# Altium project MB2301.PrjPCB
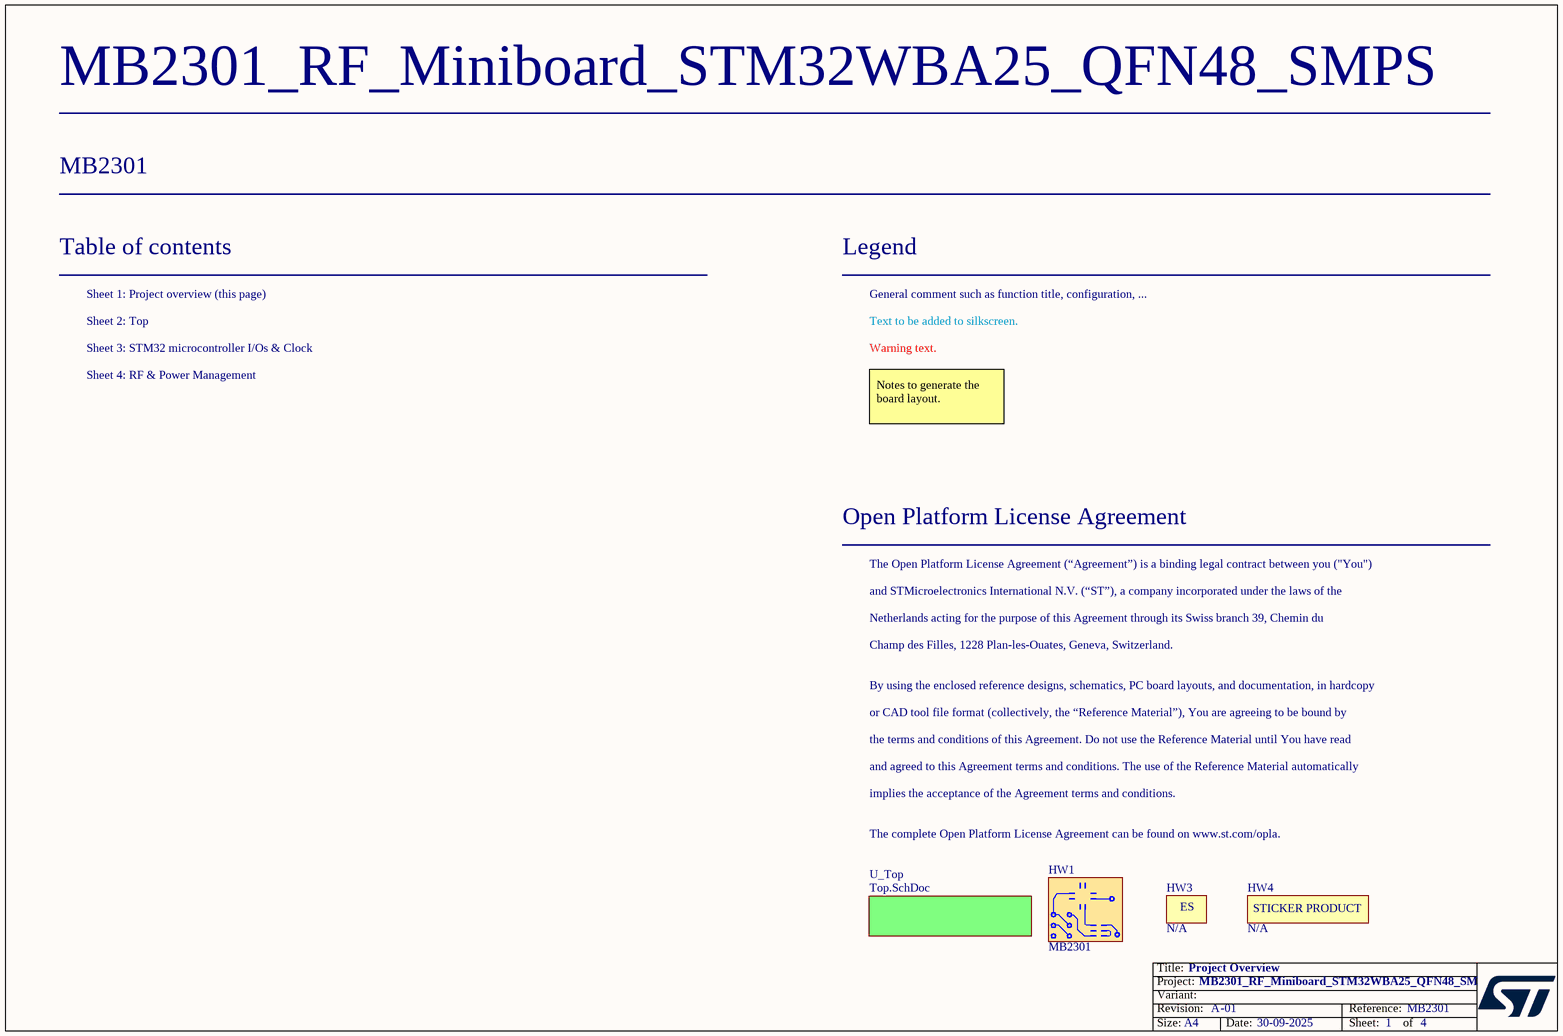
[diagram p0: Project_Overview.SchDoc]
Board_Assembly_Revision: 01; Board_Document_Date: 30-09-2025; Board_Name: MB2301_RF_Miniboard_STM32WBA25_QFN48_SMPS; Board_PCB_Revision: A; Board_Reference: MB2301
4 sheets, 104 parts. Net scope: flat (ports and power ports of the same name join across sheets).
Board file: MB2301.PcbDoc
Sheets:
  Project_Overview.SchDoc
    U_Top = Top.SchDoc
      STM32 microcontroller I/Os & Clock = MCU.SchDoc
      RF & Power Management Schematic = RF&Power_Management.SchDoc

## Sheet Project_Overview.SchDoc: Project Overview
size A4; Date: Not used; ApprovedBy: Not used; CheckedBy: Not used; Author: Not used; CompanyName: STMicroelectronics; DrawnBy: Not used; Engineer: Not used; Organization: Not used; Address1: Not used; Address2: Not used; Address3: Not used; Address4: Not used; DocumentNumber: 1; Revision: Not used; SheetNumber: 1; SheetTotal: 4

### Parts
HW1  MB2301  (mechanical)
HW3  STICKER_ES  [STICKER_ES_6X6]  (value not drawn)  (no BOM)
HW4  STICKER_PRODUCT  [STICKER_PRODUCT_25X9]  (value not drawn)  (no BOM)

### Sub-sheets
U_Top = Top.SchDoc: no entries

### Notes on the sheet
- Table of contents
- Sheet 1: Project overview (this page)
- Legend
- General comment such as function title, configuration, ...
- Sheet 2: Top
- Sheet 3: STM32 microcontroller I/Os & Clock
- Sheet 4: RF & Power Management
- Text to be added to silkscreen.
- Warning text.
- Notes to generate the board layout.
- Open Platform License Agreement
- The Open Platform License Agreement (“Agreement”) is a binding legal contract between you ("You")
- and STMicroelectronics International N.V. (“ST”), a company incorporated under the laws of the
- Netherlands acting for the purpose of this Agreement through its Swiss branch 39, Chemin du
- Champ des Filles, 1228 Plan-les-Ouates, Geneva, Switzerland.
- By using the enclosed reference designs, schematics, PC board layouts, and documentation, in hardcopy
- or CAD tool file format (collectively, the “Reference Material”), You are agreeing to be bound by
- the terms and conditions of this Agreement. Do not use the Reference Material until You have read
- and agreed to this Agreement terms and conditions. The use of the Reference Material automatically
- implies the acceptance of the Agreement terms and conditions.
- The complete Open Platform License Agreement can be found on www.st.com/opla.

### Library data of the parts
HW1 = MB2301: PCB2301 for include in BOM; Internal_Part_Number: MCD-04979; Manufacturer: FASTPRINT; Part_Preference: Recommended; ECCN_EU: NEC°°°; ECCN_US: EAR99°°°; CCATS: Not Required
HW3 = MCD-00234: Sticker ES, 6x6mm; Part_Type: Misc; Part_Preference: Recommended; Component_Country_Of_Origin: Unknown; ShowFields: YES; ID: 2634
HW4 = MCD-00547: Sticker product, 25x9mm; Part_Type: Misc; Part_Preference: Recommended; Component_Country_Of_Origin: Unknown; ShowFields: YES; ID: 3197

## Sheet Top.SchDoc: Top Schematic
size A4; Date: Not used; ApprovedBy: Not used; CheckedBy: Not used; Author: Not used; CompanyName: STMicroelectronics; DrawnBy: Not used; Engineer: Not used; Organization: Not used; Address1: Not used; Address2: Not used; Address3: Not used; Address4: Not used; DocumentNumber: 2; Revision: Not used; SheetNumber: 2; SheetTotal: 4
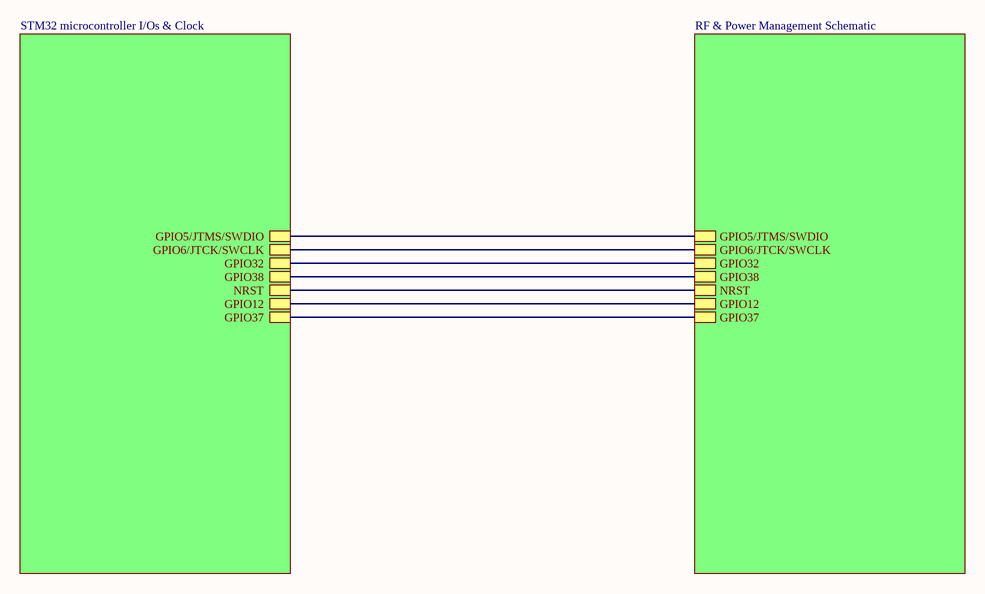
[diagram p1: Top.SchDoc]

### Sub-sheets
RF & Power Management Schematic = RF&Power_Management.SchDoc: GPIO5/JTMS/SWDIO, GPIO6/JTCK/SWCLK, GPIO32, GPIO38, NRST, GPIO12, GPIO37
STM32 microcontroller I/Os & Clock = MCU.SchDoc: GPIO37, GPIO5/JTMS/SWDIO, GPIO6/JTCK/SWCLK, GPIO32, GPIO38, NRST, GPIO12

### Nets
(unnamed): sheet STM32 microcontroller I/Os & Clock/GPIO37, sheet RF & Power Management Schematic/GPIO37
(unnamed): sheet STM32 microcontroller I/Os & Clock/GPIO5/JTMS/SWDIO, sheet RF & Power Management Schematic/GPIO5/JTMS/SWDIO  [a separate net that carries the same name]
(unnamed): sheet STM32 microcontroller I/Os & Clock/GPIO6/JTCK/SWCLK, sheet RF & Power Management Schematic/GPIO6/JTCK/SWCLK  [a separate net that carries the same name]
(unnamed): sheet STM32 microcontroller I/Os & Clock/GPIO32, sheet RF & Power Management Schematic/GPIO32  [a separate net that carries the same name]
(unnamed): sheet STM32 microcontroller I/Os & Clock/GPIO38, sheet RF & Power Management Schematic/GPIO38  [a separate net that carries the same name]
(unnamed): sheet STM32 microcontroller I/Os & Clock/NRST, sheet RF & Power Management Schematic/NRST  [a separate net that carries the same name]
(unnamed): sheet STM32 microcontroller I/Os & Clock/GPIO12, sheet RF & Power Management Schematic/GPIO12  [a separate net that carries the same name]

## Sheet MCU.SchDoc: STM32 microcontroller I/Os & Clock
size A4; Date: Not used; ApprovedBy: Not used; CheckedBy: Not used; Author: Not used; CompanyName: STMicroelectronics; DrawnBy: Not used; Engineer: Not used; Organization: Not used; Address1: Not used; Address2: Not used; Address3: Not used; Address4: Not used; DocumentNumber: 3; Revision: Not used; SheetNumber: 3; SheetTotal: 4
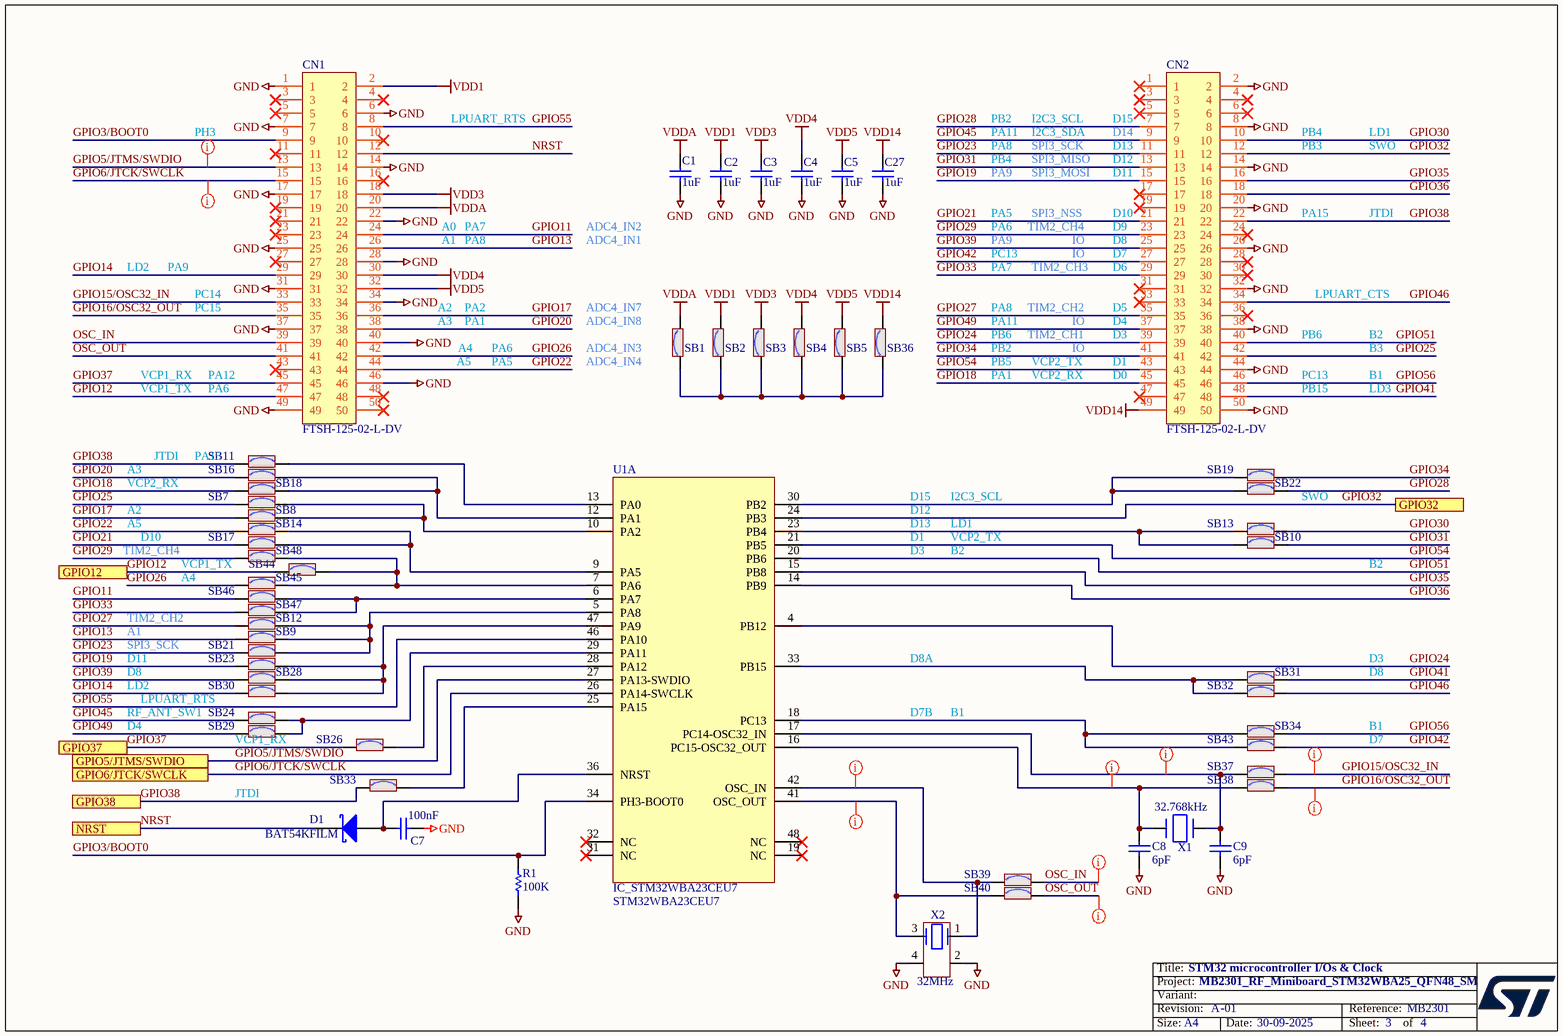
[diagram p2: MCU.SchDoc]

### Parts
C1  value 1uF  [C0402]  (hidden comment: Capacitor)
C2  value 1uF  [C0402]  (hidden comment: Capacitor)
C3  value 1uF  [C0402]  (hidden comment: Capacitor)
C4  value 1uF  [C0402]  (hidden comment: Capacitor)
C5  value 1uF  [C0402]  (hidden comment: Capacitor)
C7  value 100nF  [C0402]  (hidden comment: Capacitor)
C8  value 6pF  [C0402]  (hidden comment: Capacitor)
C9  value 6pF  [C0402]  (hidden comment: Capacitor)
C27  value 1uF  [C0402]  (hidden comment: Capacitor)
CN1  FTSH-125-02-L-DV  [Footprint sent by email... (Footprint FTSH-125-02-L-DV)]
CN2  FTSH-125-02-L-DV  [Footprint sent by email... (Footprint FTSH-125-02-L-DV)]
D1  value BAT54KFILM  [DIO_SOD523_1A_2K]  (hidden comment: SCHOTTKY_1A_2K)
R1  value 100K  [R0402]  (hidden comment: Resistor)
SB1  SB_ON  [SOLDER-BRIDGE_R0402-0R]  (value not drawn)
SB2  SB_ON  [SOLDER-BRIDGE_R0402-0R]  (value not drawn)
SB3  SB_ON  [SOLDER-BRIDGE_R0402-0R]  (value not drawn)
SB4  SB_ON  [SOLDER-BRIDGE_R0402-0R]  (value not drawn)
SB5  SB_ON  [SOLDER-BRIDGE_R0402-0R]  (value not drawn)
SB7  SB_ON  [SOLDER-BRIDGE_R0402-0R]  (value not drawn)
SB8  SB_ON  [SOLDER-BRIDGE_R0402-0R]  (value not drawn)
SB9  SB_ON  [SOLDER-BRIDGE_R0402-0R]  (value not drawn)
SB10  SB_ON  [SOLDER-BRIDGE_R0402-0R]  (value not drawn)
SB11  SB_ON  [SOLDER-BRIDGE_R0402-0R]  (value not drawn)
SB12  SB_ON  [SOLDER-BRIDGE_R0402-0R]  (value not drawn)
SB13  SB_ON  [SOLDER-BRIDGE_R0402-0R]  (value not drawn)
SB14  SB_ON  [SOLDER-BRIDGE_R0402-0R]  (value not drawn)
SB16  SB_ON  [SOLDER-BRIDGE_R0402-0R]  (value not drawn)
SB17  SB_ON  [SOLDER-BRIDGE_R0402-0R]  (value not drawn)
SB18  SB_ON  [SOLDER-BRIDGE_R0402-0R]  (value not drawn)
SB19  SB_ON  [SOLDER-BRIDGE_R0402-0R]  (value not drawn)
SB21  SB_ON  [SOLDER-BRIDGE_R0402-0R]  (value not drawn)
SB22  SB_ON  [SOLDER-BRIDGE_R0402-0R]  (value not drawn)
SB23  SB_ON  [SOLDER-BRIDGE_R0402-0R]  (value not drawn)
SB24  SB_ON  [SOLDER-BRIDGE_R0402-0R]  (value not drawn)
SB26  SB_ON  [SOLDER-BRIDGE_R0402-0R]  (value not drawn)
SB28  SB_ON  [SOLDER-BRIDGE_R0402-0R]  (value not drawn)
SB29  SB_ON  [SOLDER-BRIDGE_R0402-0R]  (value not drawn)
SB30  SB_ON  [SOLDER-BRIDGE_R0402-0R]  (value not drawn)
SB31  SB_ON  [SOLDER-BRIDGE_R0402-0R]  (value not drawn)
SB32  SB_ON  [SOLDER-BRIDGE_R0402-0R]  (value not drawn)
SB33  SB_ON  [SOLDER-BRIDGE_R0402-0R]  (value not drawn)
SB34  SB_ON  [SOLDER-BRIDGE_R0402-0R]  (value not drawn)
SB36  SB_ON  [SOLDER-BRIDGE_R0402-0R]  (value not drawn)
SB37  SB_ON  [SOLDER-BRIDGE_R0402-0R]  (value not drawn)
SB38  SB_ON  [SOLDER-BRIDGE_R0402-0R]  (value not drawn)
SB39  SB_ON  [SOLDER-BRIDGE_R0402-0R]  (value not drawn)
SB40  SB_ON  [SOLDER-BRIDGE_R0402-0R]  (value not drawn)
SB43  SB_ON  [SOLDER-BRIDGE_R0402-0R]  (value not drawn)
SB44  SB_ON  [SOLDER-BRIDGE_R0402-0R]  (value not drawn)
SB45  SB_ON  [SOLDER-BRIDGE_R0402-0R]  (value not drawn)
SB46  SB_ON  [SOLDER-BRIDGE_R0402-0R]  (value not drawn)
SB47  SB_ON  [SOLDER-BRIDGE_R0402-0R]  (value not drawn)
SB48  SB_ON  [SOLDER-BRIDGE_R0402-0R]  (value not drawn)
U1  IC_STM32WBA23CEU7  value STM32WBA23CEU7  [ICC_UFQFPN48-EPAD_7X7_H0P55_P050]  (part A of 3)
X1  value 32.768kHz  [CRY_NX1610SE_2P]  (hidden comment: XTAL_2_PINS)
X2  value 32MHz  [CRY_NX1612SA_4P]  (hidden comment: XTAL_4_PINS)

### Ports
GPIO5/JTMS/SWDIO, GPIO6/JTCK/SWCLK, GPIO12, GPIO32, GPIO37, GPIO38, NRST

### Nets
GND: C1.1 C2.1 C3.1 C4.1 C5.1 C7.1 C8.2 C9.1 C27.1 CN1.1 CN1.6 CN1.7 CN1.14 CN1.17 CN1.22 CN1.25 CN1.28 CN1.31 CN1.34 CN1.37 CN1.40 CN1.46 CN1.49 CN2.2 CN2.8 CN2.14 CN2.20 CN2.26 CN2.32 CN2.38 CN2.44 CN2.50 R1.2 X2.2 X2.4
VDD1: C2.2 CN1.2 SB2.2
VDD3: C3.2 CN1.18 SB3.2
VDD4: C4.2 CN1.30 SB4.2
VDD5: C5.2 CN1.32 SB5.2
VDD14: C27.2 CN2.49 SB36.2
VDDA: C1.2 CN1.20 SB1.2
GPIO3/BOOT0: CN1.9 R1.1 U1.34(PH3-BOOT0)
GPIO5/JTMS/SWDIO: CN1.13 U1.27(PA13-SWDIO) ; port GPIO5/JTMS/SWDIO
GPIO6/JTCK/SWCLK: CN1.15 U1.26(PA14-SWCLK) ; port GPIO6/JTCK/SWCLK
GPIO11: CN1.24 SB46.1
GPIO12: CN1.47 SB44.1 ; port GPIO12
GPIO13: CN1.26 SB9.1
GPIO14: CN1.29 SB30.1
GPIO15/OSC32_IN: CN1.33 SB37.2
GPIO16/OSC32_OUT: CN1.35 SB38.2
GPIO17: CN1.36 SB8.1
GPIO18: CN2.45 SB18.1
GPIO19: CN2.15 SB23.1
GPIO20: CN1.38 SB16.1
GPIO21: CN2.21 SB17.1
GPIO22: CN1.44 SB14.1
GPIO23: CN2.11 SB21.1
GPIO24: CN2.39 U1.4(PB12)
GPIO25: CN2.42 SB7.1
GPIO26: CN1.42 SB45.1
GPIO27: CN2.35 SB12.1
GPIO28: CN2.7 SB22.2
GPIO29: CN2.23 SB48.1
GPIO30: CN2.10 SB13.2
GPIO31: CN2.13 SB10.2
GPIO32: CN2.12 U1.24(PB3) ; port GPIO32
GPIO33: CN2.29 SB47.1
GPIO34: CN2.41 SB19.2
GPIO35: CN2.16 U1.15(PB8)
GPIO36: CN2.18 U1.14(PB9)
GPIO37: CN1.45 SB26.1 ; port GPIO37
GPIO38: CN2.22 SB11.1 SB33.1 ; port GPIO38
GPIO39: CN2.25 SB28.1
GPIO41: CN2.48 SB31.2
GPIO42: CN2.27 SB43.2
GPIO45: CN2.9 SB24.1
GPIO46: CN2.34 SB32.2
GPIO49: CN2.37 SB29.1
GPIO51: CN2.40 U1.20(PB6)
GPIO54: CN2.43 U1.21(PB5)
GPIO55: CN1.8 U1.46(PA10)
GPIO56: CN2.46 SB34.2
NRST: CN1.12 D1.2(K) ; port NRST
OSC_IN: CN1.39 SB39.2
OSC_OUT: CN1.41 SB40.2
NetC7_2: C7.2 D1.1(A) U1.36(NRST)
NetC8_1: C8.1 SB38.1 U1.16(PC15-OSC32_OUT) X1.2(X2)
NetC9_2: C9.2 SB37.1 U1.17(PC14-OSC32_IN) X1.1(X1)
NetSB1_1: SB1.1 SB2.1 SB3.1 SB4.1 SB5.1 SB36.1
NetSB7_2: SB7.2 SB8.2 U1.10(PA2)
NetSB9_2: SB9.2 SB12.2 SB21.2 U1.5(PA8)
NetSB10_1: SB10.1 SB13.1 U1.23(PB4)
NetSB11_2: SB11.2 U1.13(PA0)
NetSB14_2: SB14.2 SB17.2 U1.9(PA5)
NetSB16_2: SB16.2 SB18.2 U1.12(PA1)
NetSB19_1: SB19.1 SB22.1 U1.30(PB2)
NetSB23_2: SB23.2 SB28.2 SB30.2 U1.47(PA9)
NetSB24_2: SB24.2 SB29.2 U1.29(PA11)
NetSB26_2: SB26.2 U1.28(PA12)
NetSB31_1: SB31.1 SB32.1 U1.33(PB15)
NetSB33_2: SB33.2 U1.25(PA15)
NetSB34_1: SB34.1 SB43.1 U1.18(PC13)
NetSB39_1: SB39.1 U1.42(OSC_IN) X2.1
NetSB40_1: SB40.1 U1.41(OSC_OUT) X2.3
NetSB44_2: SB44.2 SB45.2 SB48.2 U1.7(PA6)
NetSB46_2: SB46.2 SB47.2 U1.6(PA7)

Not connected (* = marked no-connect by the designer): CN1 3* 4* 5* 10* 11* 16* 19* 21* 23* 27* 43* 48* 50*; CN2 1* 3* 4* 5* 6* 17* 19* 24* 28* 30* 31* 33* 36* 47*; U1 19(NC)* 31(NC)* 32(NC)* 48(NC)*

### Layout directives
net class X2: NetSB39_1, NetSB40_1, OSC_IN, OSC_OUT
net class X1: GPIO15/OSC32_IN, GPIO16/OSC32_OUT, NetC8_1, NetC9_2
net class SWCLK: GPIO6/JTCK/SWCLK
net class SWDIO: GPIO5/JTMS/SWDIO

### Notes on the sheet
- PH3
- LPUART_RTS
- PA8
- PB2
- PB4
- PA11
- PA9
- I2C3_SDA
- I2C3_SCL
- SPI3_SCK
- SPI3_MISO
- SPI3_MOSI
- (near CN2) D11
- (near CN2) D13
- (near CN2) D15
- (near CN2) D12
- (near CN2) D14
- PB3
- SWO
- LD1
- A0
- A1
- PA7
- ADC4_IN2
- ADC4_IN1
- PA5
- PA6
- TIM2_CH4
- SPI3_NSS
- IO
- (near CN2) D10
- (near CN2) D9
- (near CN2) D8
- PA15
- JTDI
- LD2
- PC14
- PC15
- A2
- PA2
- (near SB1) ADC4_IN7
- PC13
- TIM2_CH2
- TIM2_CH3
- (near CN2) D7
- (near CN2) D5
- (near CN2) D6
- LPUART_CTS
- VCP1_RX
- PA12
- A3
- A5
- A4
- PA1
- (near SB1) ADC4_IN8
- (near SB1) ADC4_IN4
- (near SB1) ADC4_IN3
- PB5
- PB6
- TIM2_CH1
- VCP2_TX
- VCP2_RX
- (near CN2) D1
- (near CN2) D4
- (near CN2) D3
- (near CN2) D0
- B1
- B2
- B3
- VCP1_TX
- PB15
- LD3
- D12
- D15
- D10
- D3
- D1
- D13
- RF_ANT_SW1
- D8
- D11
- D7B
- D8A
- D4
- (near SB29) VCP1_RX
- D7

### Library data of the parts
C1-C5 C27 = MCD-01722: Capacitor, MLCC, 1uF, 10V, X5R, +/-10%, 0402, T=0.5mm; Part_Preference: Recommended; Manufacturer: YAGEO; Manufacturer_Part_Number: CC0402KRX5R6BB105; Component_Country_Of_Origin: China
C7 = MCD-00006: Capacitor, MLCC, 100nF, 16V, X7R, +/-10%, 0402, T=0.5mm; Manufacturer_Part_Number: CC0402KRX7R7BB104; Manufacturer: YAGEO; Alternate_Manufacturer_Part_Number: GCM155R71C104KA55D; Alternate_Manufacturer: MURATA; Part_Preference: Recommended; Order_Code_RS: 616-9701
C8 C9 = MCD-03185: Capacitor, MLCC, 6 pF, 50V, NPO, ±0,25pF, 0402, T=0.5mm; Part_Preference: Recommended; Manufacturer: MURATA; Manufacturer_Part_Number: GJM1555C1H6R0CB01; Order_Code_RS: 170-6040; ShowFields: YES; ID: 5301
CN1 CN2 = MCD-02746: Header 25x2, 12.7mm, SMT,height 4.83mm; Part_Type: Connector; Part_Preference: Recommended; Manufacturer: SAMTEC; Order_code_RS: NA; ShowFields: YES; ID: 4858
D1 = MCD-01677: Small signal Schottky diodes; Part_Type: Diode; Manufacturer: STMICROELECTRONICS; BMS_Part_Number: 9151123; Part_Preference: Recommended; Manufacturer_HQ_COO: EU
R1 = MCD-00059: Resistor, 100K, 0402, +/-1%, 1/16W; Part_Preference: Recommended; Manufacturer: YAGEO; Manufacturer_Part_Number: RC0402FR-07100KL; Component_Country_Of_Origin: China
SB1-SB5 SB7-SB14 SB16-SB19 SB21-SB24 SB26 SB28-SB34 SB36-SB40 SB43-SB48 = MCD-01618: Solder Bridge 0402 ON; Part_Type: Misc; Part_Preference: Recommended; Manufacturer: YAGEO; Manufacturer_Part_Number: RC0402JR-070RL; Order_Code_RS: 618-5804; Component_Country_Of_Origin: China
U1 = MCD-04358: MCU, ARM Cortex-M33 32-bit, 512KB Flash, 96KB RAM, Crypto, SMPS; Part_Type: IC; Part_Preference: Recommended; Manufacturer: STMICROELECTRONICS; Component_Country_Of_Origin: Unknown; ShowFields: YES; ID: 6474
X1 = MCD-02579: Crystal, 32.768kHz, 6pF, +/-20ppm, 70KR, 1.6x1mm; Part_Type: Crystal_Osc; Part_Preference: Recommended; Manufacturer: NDK; Manufacturer_Part_Number: NX1610SE-32.768KHZ-EXS00A-MU01501
X2 = MCD-02578: Crystal, 32MHz, 8pF, +/-10ppm, 40R, 1612(metric), T=0.3mm; Part_Type: Crystal_Osc; Part_Preference: Recommended; Manufacturer: NDK; Manufacturer_Part_Number: NX1612SA-32MHZ-EXS00A-CS09166

## Sheet RF&Power_Management.SchDoc: RF & Power Management Schematic
size A4; Date: Not used; ApprovedBy: Not used; CheckedBy: Not used; Author: Not used; CompanyName: STMicroelectronics; DrawnBy: Not used; Engineer: Not used; Organization: Not used; Address1: Not used; Address2: Not used; Address3: Not used; Address4: Not used; DocumentNumber: 4; Revision: Not used; SheetNumber: 4; SheetTotal: 4
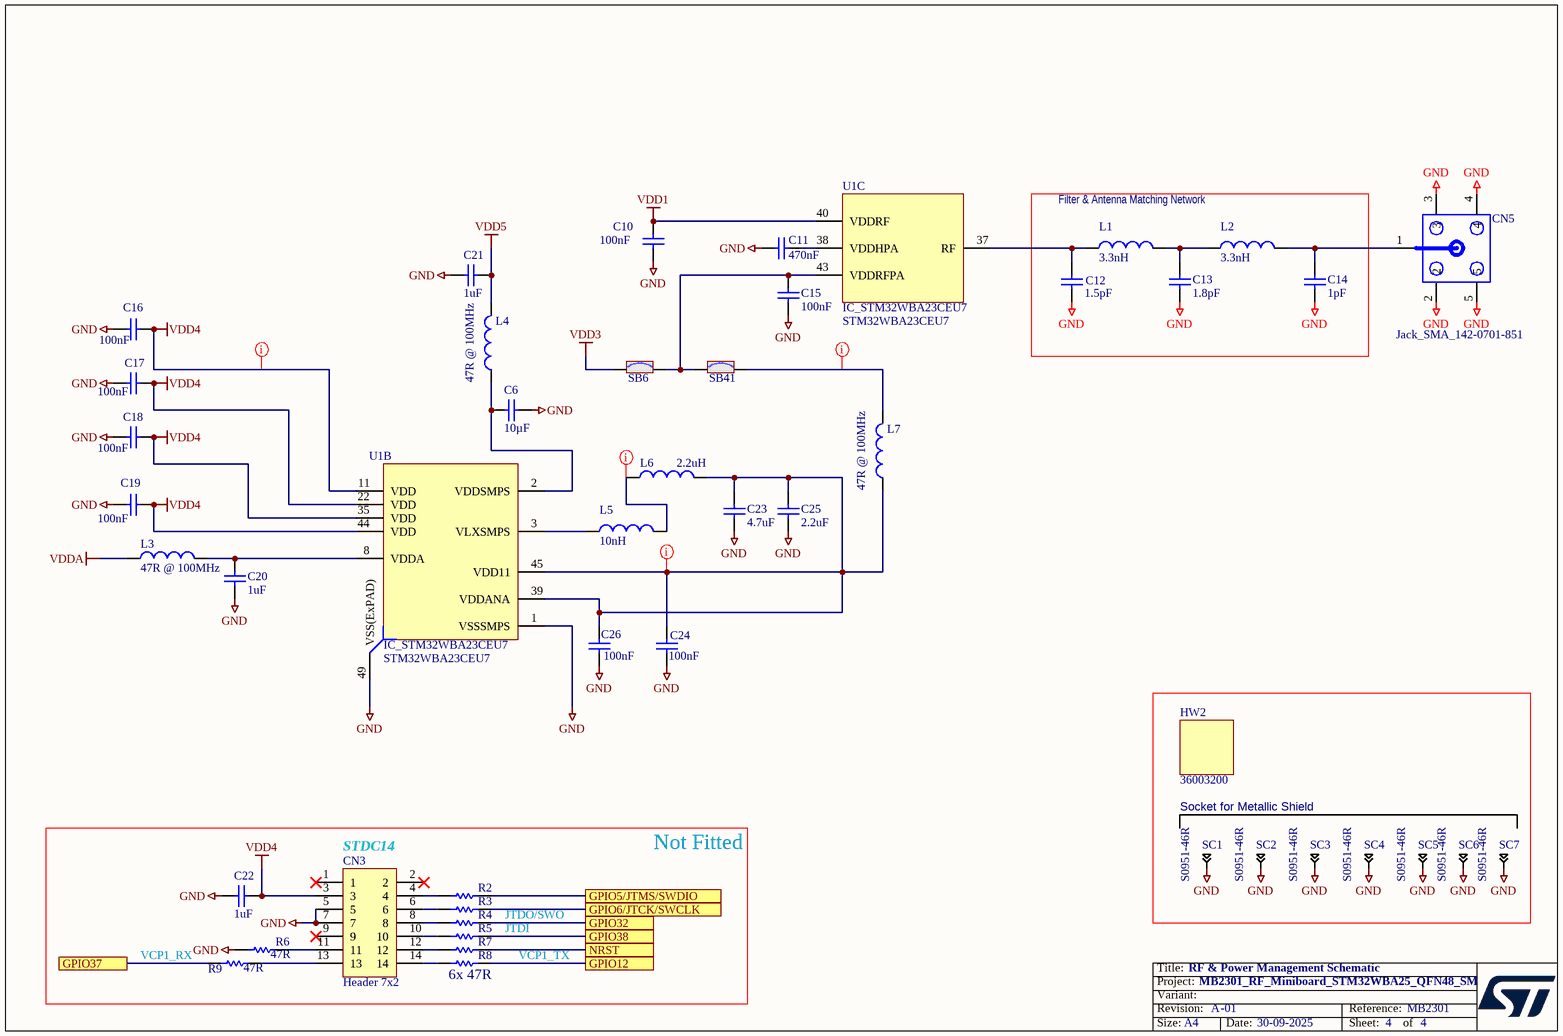
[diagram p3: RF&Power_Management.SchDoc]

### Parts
C6  value 10µF  [C0603_H0P8]  (hidden comment: Capacitor)
C10  value 100nF  [C0402]  (hidden comment: Capacitor)
C11  value 470nF  [C0603]  (hidden comment: Capacitor)
C12  value 1.5pF  [C0402]  (hidden comment: Capacitor)
C13  value 1.8pF  [C0402]  (hidden comment: Capacitor)
C14  value 1pF  [C0402]  (hidden comment: Capacitor)
C15  value 100nF  [C0402]  (hidden comment: Capacitor)
C16  value 100nF  [C0402]  (hidden comment: Capacitor)
C17  value 100nF  [C0402]  (hidden comment: Capacitor)
C18  value 100nF  [C0402]  (hidden comment: Capacitor)
C19  value 100nF  [C0402]  (hidden comment: Capacitor)
C20  value 1uF  [C0402]  (hidden comment: Capacitor)
C21  value 1uF  [C0402]  (hidden comment: Capacitor)
C22  value 1uF  [C0603]  (hidden comment: Capacitor)
C23  value 4.7uF  [C0402]  (hidden comment: Capacitor)
C24  value 100nF  [C0402]  (hidden comment: Capacitor)
C25  value 2.2uF  [C0402]  (hidden comment: Capacitor)
C26  value 100nF  [C0402]  (hidden comment: Capacitor)
CN3  Header 7x2  [CON_SAMTEC_FTSH-107-01-L-DV-K-A]
CN5  value Jack_SMA_142-0701-851  [142-0701-851]  (hidden comment: SMA-J-P-H-ST-EM1)
HW2  value 36003200  [SHIELD_WURTH_36003200_21P8X21P8]  (hidden comment: Shield Cover)
L1  value 3.3nH  [C0402]  (hidden comment: Inductor)
L2  value 3.3nH  [C0402]  (hidden comment: Inductor)
L3  value 47R @ 100MHz  [IND_0603_H0P8]  (hidden comment: Inductor)
L4  value 47R @ 100MHz  [IND_0603_H0P8]  (hidden comment: Inductor)
L5  value 10nH  [C0402]  (hidden comment: Inductor)
L6  value 2.2uH  [L0805_H0P9]  (hidden comment: Inductor)
L7  value 47R @ 100MHz  [IND_0603_H0P8]  (hidden comment: Inductor)
R2  Resistor  [R0402]  (value not drawn)
R3  Resistor  [R0402]  (value not drawn)
R4  Resistor  [R0402]  (value not drawn)
R5  Resistor  [R0402]  (value not drawn)
R6  value 47R  [R0402]  (hidden comment: Resistor)
R7  Resistor  [R0402]  (value not drawn)
R8  Resistor  [R0402]  (value not drawn)
R9  value 47R  [R0402]  (hidden comment: Resistor)
SB6  SB_ON  [SOLDER-BRIDGE_R0402-0R]  (value not drawn)
SB41  SB_ON  [SOLDER-BRIDGE_R0402-0R]  (value not drawn)
SC1  value S0951-46R  [CLIP_HARWIN_S0951-46R]  (hidden comment: Shield-clip_S0951-46R)
SC2  value S0951-46R  [CLIP_HARWIN_S0951-46R]  (hidden comment: Shield-clip_S0951-46R)
SC3  value S0951-46R  [CLIP_HARWIN_S0951-46R]  (hidden comment: Shield-clip_S0951-46R)
SC4  value S0951-46R  [CLIP_HARWIN_S0951-46R]  (hidden comment: Shield-clip_S0951-46R)
SC5  value S0951-46R  [CLIP_HARWIN_S0951-46R]  (hidden comment: Shield-clip_S0951-46R)
SC6  value S0951-46R  [CLIP_HARWIN_S0951-46R]  (hidden comment: Shield-clip_S0951-46R)
SC7  value S0951-46R  [CLIP_HARWIN_S0951-46R]  (hidden comment: Shield-clip_S0951-46R)
U1  IC_STM32WBA23CEU7  value STM32WBA23CEU7  [ICC_UFQFPN48-EPAD_7X7_H0P55_P050]  (parts B,C of 3)

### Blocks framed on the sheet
Filter & Antenna Matching Network: C12-C14 L1 L2
Socket for Metallic Shield: HW2 SC1-SC7
Not Fitted: C22 CN3 R2-R9

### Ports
GPIO5/JTMS/SWDIO, GPIO6/JTCK/SWCLK, GPIO12, GPIO32, GPIO37, GPIO38, NRST

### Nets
GND: C6.2 C10.2 C11.1 C12.2 C13.1 C14.2 C15.2 C16.2 C17.2 C18.2 C19.2 C20.1 C21.2 C22.1 C23.1 C24.2 C25.2 C26.2 CN3.5 CN3.7 CN5.2 CN5.3 CN5.4 CN5.5 R6.1 SC1.1 SC2.1 SC3.1 SC4.1 SC5.1 SC6.1 SC7.1 U1.1(VSSSMPS) U1.49(VSS(ExPAD))
VDD1: C10.1 U1.40(VDDRF)
VDD3: SB6.1
VDD4: C16.1 C17.1 C18.1 C19.1 C22.2 CN3.3 U1.11(VDD) U1.22(VDD) U1.35(VDD) U1.44(VDD)
VDD5: C21.1 L4.2
VDDA: L3.1
GPIO5/JTMS/SWDIO: R2.2 ; port GPIO5/JTMS/SWDIO
GPIO6/JTCK/SWCLK: R3.2 ; port GPIO6/JTCK/SWCLK
GPIO12: R8.2 ; port GPIO12
GPIO32: R4.2 ; port GPIO32
GPIO37: R9.1 ; port GPIO37
GPIO38: R5.2 ; port GPIO38
NRST: R7.2 ; port NRST
NetC6_1: C6.1 L4.1 U1.2(VDDSMPS)
NetC11_2: C11.2 U1.38(VDDHPA)
NetC12_1: C12.1 L1.1 U1.37(RF)
NetC13_2: C13.2 L1.2 L2.1
NetC14_1: C14.1 CN5.1 L2.2
NetC15_1: C15.1 SB6.2 SB41.1 U1.43(VDDRFPA)
NetC20_2: C20.2 L3.2 U1.8(VDDA)
NetC23_2: C23.2 C24.1 C25.1 C26.1 L6.2 L7.1 U1.39(VDDANA) U1.45(VDD11)
NetCN3_4: CN3.4 R2.1
NetCN3_6: CN3.6 R3.1
NetCN3_8: CN3.8 R4.1
NetCN3_10: CN3.10 R5.1
NetCN3_11: CN3.11 R6.2
NetCN3_12: CN3.12 R7.1
NetCN3_13: CN3.13 R9.2
NetCN3_14: CN3.14 R8.1
NetL5_1: L5.1 U1.3(VLXSMPS)
NetL5_2: L5.2 L6.1
NetL7_2: L7.2 SB41.2

Not connected (* = marked no-connect by the designer): CN3 1* 2* 9*

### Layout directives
net class DC/DC: NetC23_2, NetL5_2, NetL7_2
net class VDD4: VDD4

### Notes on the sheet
- (near CN3) STDC14
- JTDO/SWO
- (near R9) VCP1_RX
- (near R8) 6x 47R
- JTDI
- VCP1_TX

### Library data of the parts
C6 = MCD-02733: Capacitor, MLCC, 10uF, 10V, X6S, +/-20%, 0603, T=1mm; Part_Preference: Recommended; Manufacturer: MURATA; Manufacturer_Part_Number: GRM188C81A106MA73; Order_Code_RS: 170-6242; Component_Country_Of_Origin: Japan; ShowFields: YES; ID: 4845
C10 C15-C19 C24 C26 = MCD-00006: as C7 on sheet MCU
C11 = MCD-01006: Capacitor, MLCC, 470nF, 16V, X7R, +/-10%, 0603, T=0.8mm; BMS_Part_Number: 9142003; Part_Preference: Recommended; Manufacturer: YAGEO; Manufacturer_Part_Number: CC0603KRX7R7BB474; Order_Code_RS: 200-6576; Component_Country_Of_Origin: China
C12 = MCD-02994: Capacitor, MLCC, 1.5pF, 50V, C0G, +/-0.25pF, 0402, T=0.5mm; Part_Preference: Recommended; Manufacturer: MURATA; Manufacturer_Part_Number: GRM1555C1H1R5CA01; Component_Country_Of_Origin: Japan°; ShowFields: YES; ID: 5110
C13 = MCD-02995: Capacitor, MLCC, 1.8pF, 50V, C0G, +/-0.25pF, 0402, T=0.5mm; Part_Preference: Recommended; Manufacturer: MURATA; Manufacturer_Part_Number: GRM1555C1H1R8CA01; Order_Code_RS: 723-5357; Component_Country_Of_Origin: Japan°; ShowFields: YES; ID: 5111
C14 = MCD-03045: Capacitor, MLCC, 1.0pF, 50V, C0G, +/-0.25pF, 0402, T=0.5mm; Part_Preference: Recommended; Manufacturer: MURATA; Manufacturer_Part_Number: GRM1555C1H1R0CA01; Component_Country_Of_Origin: Japan°; ShowFields: YES; ID: 5161
C20 C21 = MCD-01722: as C1 on sheet MCU
C22 = MCD-00010: Capacitor, MLCC, 1uF, 16V, X5R, 10%, 0603, T=0,8mm; Manufacturer_Part_Number: CC0603KRX5R7BB105; Manufacturer: YAGEO; Provided_By: Subcon; Initial_Board_Reference: MB1274
C23 = MCD-01356: Capacitor, MLCC, 4.7uF, 6V3, X5R, +/-20%, 0402, T=0.5mm; Part_Preference: Recommended; Manufacturer: MURATA; Manufacturer_Part_Number: GRM155R60J475ME47; Order_Code_RS: 814-5230; Component_Country_Of_Origin: Japan; ShowFields: YES; ID: 3456
C25 = MCD-01823: Capacitor, MLCC, 2.2uF, 6V3, X5R,+/-10%, 0402, T=0.5mm; Part_Preference: Recommended; Manufacturer: MURATA; Manufacturer_Part_Number: GRM155R60J225KE95D; Order_Code_RS: 172-6478; Component_Country_Of_Origin: Japan; ShowFields: YES; ID: 3923
CN3 = MCD-01531: Header, 7x2, 1.27mm, VR, T=5.97mm, FTSH series STDC14 without Alignment Pin; Part_Type: Connector; Part_Preference: Recommended; Manufacturer: SAMTEC; Manufacturer_Part_Number: FTSH-107-01-L-DV-K; Order_Code_RS: 179-9021; Component_Country_Of_Origin: China, Costa Rica, Malaysia, United States, Vietnam
CN5 = MCD-02072: Jack_SMA, VR, PCB edge, 50R, T=7.92mm; Part_Type: Connector; Part_Preference: Recommended; Manufacturer: CINCH; Order_Code_RS: 885-7532; Component_Country_Of_Origin: USA°°; ShowFields: YES; ID: 4172
HW2 = MCD-04686: RF Shield cover, 21.5x21.5x3.3mm; Part_Type: Misc; Part_Preference: Recommended; Manufacturer: WURTH ELEKTRONIK; Order_Code_RS: 773-7282; Component_Country_Of_Origin: Germany°; ShowFields: YES; ID: 6802
L1 L2 = MCD-03001: Inductor, 3.3nH, +/-0.3nH, 800 mA, 0.125Ohm, 0402, T=0.5mm; Part_Preference: Recommended; Manufacturer: MURATA; Manufacturer_Part_Number: LQG15HS3N3S02; Component_Country_Of_Origin: Japan°; ShowFields: YES; ID: 5117
L3 L4 L7 = MCD-03831: Ferrite bead, 47R @ 100MHz, +/-25%, 3.5A, 0R02, 0603, T=0.8mm; Part_Preference: Recommended; Manufacturer: TAIYO YUDEN; Manufacturer_Part_Number: LSMGA160808T470RG; Component_Country_Of_Origin: Unknown; ShowFields: YES; ID: 5947
L5 = MCD-03035: Inductor, 10nH, +/-2%, 500 mA, 0.26Ohm, 0402, T=0.5mm; Part_Preference: Recommended; Manufacturer: MURATA; Manufacturer_Part_Number: LQG15HS10NJ02D; Order_Code_RS: 124-8162; ShowFields: YES; ID: 5151
L6 = MCD-03791: Inductor, 2.2uH, +/-20%, 1.8A, 0R138, 0805, T=0.8mm; Part_Preference: Recommended; Manufacturer: MURATA; Manufacturer_Part_Number: DFE21CCN2R2MELL; Component_Country_Of_Origin: Vietnam; ShowFields: YES; ID: 5907
R2-R9 = MCD-00481: Resistor,47R,0402,1%,1/16W; Manufacturer_Part_Number: RC0402FR-0747RL; Manufacturer: YAGEO; Provided_By: Subcon
SB6 SB41 = MCD-01618: as SB1 on sheet MCU
SC1-SC7 = MCD-01587: shield clip Harwin S0951-46R to fix RF shielded cavity; Part_Type: Misc; Part_Preference: Recommended; Component_Country_Of_Origin: South Korea
U1 = MCD-04358: as U1 on sheet MCU

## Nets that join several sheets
GND: MCU (35 pins), RF&Power_Management (34 pins)
VDD1: MCU (C2.2 CN1.2 SB2.2), RF&Power_Management (C10.1 U1.40)
VDD3: MCU (C3.2 CN1.18 SB3.2), RF&Power_Management (SB6.1)
VDD4: MCU (C4.2 CN1.30 SB4.2), RF&Power_Management (10 pins)
VDD5: MCU (C5.2 CN1.32 SB5.2), RF&Power_Management (C21.1 L4.2)
VDDA: MCU (C1.2 CN1.20 SB1.2), RF&Power_Management (L3.1)
GPIO5/JTMS/SWDIO: MCU (CN1.13 U1.27), RF&Power_Management (R2.2)
GPIO6/JTCK/SWCLK: MCU (CN1.15 U1.26), RF&Power_Management (R3.2)
GPIO12: MCU (CN1.47 SB44.1), RF&Power_Management (R8.2)
GPIO32: MCU (CN2.12 U1.24), RF&Power_Management (R4.2)
GPIO37: MCU (CN1.45 SB26.1), RF&Power_Management (R9.1)
GPIO38: MCU (CN2.22 SB11.1 SB33.1), RF&Power_Management (R5.2)
NRST: MCU (CN1.12 D1.2), RF&Power_Management (R7.2)

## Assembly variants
WBA23CE: not fitted C25 C? CN3 R? R? R? R? R? R? R? R? SB1 SB2 SB3 SB4 SB5 SB6 SB8 SB9 SB11 SB12 SB13 SB14 SB18 SB19 SB28 SB32 SB36 SB37 SB38 SB39 SB40 SB43 SB45 SB47 SB48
